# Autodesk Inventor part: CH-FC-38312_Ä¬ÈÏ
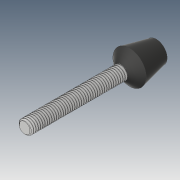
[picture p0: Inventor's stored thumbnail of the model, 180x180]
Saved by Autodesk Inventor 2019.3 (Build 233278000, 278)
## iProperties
Created: 2010-06
Part Number: CH-FC-38312_Ä¬ÈÏ
Material: Ogólny
Document SubType Name: Modeling
Designer: CADENGINEERING4
Density: 1 g/cm^3
Appearance: Domyślna
Author: CADENGINEERING4
Revision Number: ÈÎºÎ
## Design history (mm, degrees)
feature "NONE"
node "Bryła1"
